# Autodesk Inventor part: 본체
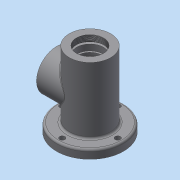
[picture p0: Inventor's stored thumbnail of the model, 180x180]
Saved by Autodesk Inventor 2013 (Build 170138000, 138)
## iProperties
Created: 2016-08
Part Number: 본체
Material: 일반
Document SubType Name: Modeling
Designer: dgall
Density: 1 g/cm^3
Author: dgall
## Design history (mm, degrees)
sketch "스케치1"
  geometry: C1 r 31 at (0, 0); 1 further point
  constraints: 1 centre point, 1 coincident
  dimensions: "d0" = 62 diameter of C1
extrude "돌출1" new body sketch "스케치1" distance "d2" = 115; taper "d3" = 0 deg
node "작업 평면1"
sketch "스케치2"
  geometry: C1 r 50 at (0, 0); 1 further point
  constraints: 1 centre point, 1 coincident
  dimensions: "d5" = 100 diameter of C1
extrude "돌출2" join sketch "스케치2" distance "d7" = 13; taper "d8" = 0 deg
node "작업 평면2"
sketch "스케치4" dims "d14" = 83
  geometry: L1 (0, 0)-(0, 41.5); C1 r 31 at (0, 0) reference; C2 r 4 at (0, 41.5)
  constraints: 2 coincident, 2 end point, 1 centre point, 1 vertical, 1 vertical alignment, 2 other
  dimensions: "d16" = 8 diameter of C2
extrude "돌출4" cut sketch "스케치4" stored distance "d17" = 13; taper "d18" = 0 deg
fillet "모깎기1" dims "d22" = 3
sketch "스케치5"
  geometry: C1 r 31 at (0, 0) reference
hole "구멍1" sketch "스케치5" at (0, 0) diameter "d23" = 40.376; stored, may be unused: countersink angle "d27" = 90 deg, drill point angle "d29" = 0 deg; dims "d24" = 6, "d25" = 4, "d26" = 2, "d28" = 9
sketch "스케치6"
  geometry: C1 r 20.188 at (0, 0) reference; C2 r 24 at (0, 0)
  constraints: 1 centre point, 1 coincident
  dimensions: "d30" = 48 diameter of C2
extrude "돌출5" cut sketch "스케치6" distance "d32" = 3; taper "d33" = 0 deg
sketch "스케치7"
  geometry: C1 r 24 at (0, 0) reference; C2 r 20 at (0, 0)
  constraints: 1 centre point, 1 coincident
  dimensions: "d34" = 40 diameter of C2
extrude "돌출6" cut sketch "스케치7" distance "d36" = 9; taper "d37" = 0 deg
fillet "모깎기2" dims "d50" = 3
sketch "스케치9"
  geometry: C1 r 20 at (0, 0) reference; C2 r 17.5 at (0, 0)
  constraints: 1 centre point, 1 coincident
  dimensions: "d52" = 35 diameter of C2
extrude "돌출7" cut sketch "스케치9" distance "d54" = 3.75; taper "d55" = 0 deg
sketch "스케치10"
  geometry: C1 r 17.5 at (0, 0) reference; C2 r 18.5 at (0, 0)
  constraints: 1 centre point, 1 coincident
  dimensions: "d56" = 37 diameter of C2
extrude "돌출8" cut sketch "스케치10" distance "d58" = 1.75; taper "d59" = 0 deg
sketch "스케치11"
  geometry: C1 r 18.5 at (0, 0) reference; C2 r 17.5 at (0, 0)
  constraints: 1 centre point, 1 coincident
  dimensions: "d60" = 35 diameter of C2
extrude "돌출9" cut sketch "스케치11" distance "d62" = 11; taper "d63" = 0 deg
chamfer "모따기1" distance "d64" = 1; stored, may be unused: second distance "d65" = 2, angle "d66" = 45 deg
sketch "스케치12"
  geometry: C1 r 16.5 at (0, 0) reference; C2 r 26 at (0, 0)
  constraints: 1 centre point, 1 coincident
  dimensions: "d67" = 52 diameter of C2
extrude "돌출10" cut sketch "스케치12" distance "d69" = 38; taper "d70" = 0 deg
sketch "스케치13"
  geometry: C1 r 26 at (0, 0) reference; C2 r 17.5 at (0, 0)
  constraints: 1 centre point, 1 coincident
  dimensions: "d71" = 35 diameter of C2
extrude "돌출11" cut sketch "스케치13" distance "d73" = 11; taper "d74" = 0 deg
chamfer "모따기2" distance "d75" = 1; stored, may be unused: second distance "d76" = 2, angle "d77" = 45 deg
sketch "스케치14"
  geometry: C1 r 17.5 at (0, 0) reference; C2 r 16.5 at (0, 0)
  constraints: 1 centre point, 1 coincident
  dimensions: "d78" = 33 diameter of C2
extrude "돌출12" cut sketch "스케치14" distance "d80" = 5; taper "d81" = 0 deg
fillet "모깎기4" dims "d82" = 3
sketch "스케치15"
  geometry: C1 r 13.5 at (0, 0) reference; C2 r 10 at (0, 0)
  constraints: 1 centre point, 1 coincident
  dimensions: "d83" = 20 diameter of C2
sketch "스케치18"
  geometry: L1 (0, 0)-(0, 37.8); L2 (21, 0)-(16, 14); L3 (16, 14)-(0, 14); L4 (-31, 0)-(31, 0) reference; L5 (21, 0)-(0, 0)
  constraints: 8 end point, 1 perpendicular, 1 point on line, 1 vertical
  dimensions: "d101" = 42 diameter of L2.start L1; "d103" = 32 diameter of L2.end L1; "d104" = 14 vertical distance of L2.start L2.end; "d105" = 0 distance from line of L4 L2.start
revolve "회전1" sketch "스케치18" stored, may be unused: angle "d106" = 90 deg
fillet "모깎기5" dims "d107" = 3
extrude "돌출16" cut sketch "스케치15" distance "d108" = 2.7; taper "d109" = 0 deg
sketch "스케치19"
  geometry: C1 r 10 at (0, 0) reference; C2 r 12.5 at (0, 0)
  constraints: 1 centre point, 1 coincident
  dimensions: "d110" = 25 diameter of C2
extrude "돌출17" cut sketch "스케치19" stored distance "d112" = 2.7; taper "d113" = 0 deg
chamfer "모따기5" distance "d114" = 0.7; stored, may be unused: second distance "d115" = 2, angle "d116" = 30 deg
node "작업 평면3"
node "작업 평면4"
node "작업 평면5"
node "작업 평면6"
sketch "스케치23"
  geometry: L1 (31, 115)-(-31, 115) reference; L2 (0, 115)-(0, 59); C1 r 30 at (0, 59); 1 further point
  constraints: 2 end point, 1 centre point, 1 coincident, 1 midpoint, 1 perpendicular
  dimensions: "d123" = 56 distance of L2.start L2.end; "d125" = 60 diameter of C1
extrude "돌출18" join sketch "스케치23" stored distance "d126" = 2.7; taper "d127" = 0 deg
sketch "스케치24"
  geometry: C1 r 30 at (0, 0) reference; C2 r 19 at (0, 0); 1 further point
  constraints: 1 centre point, 1 coincident
  dimensions: "d128" = 38 diameter of C2
extrude "돌출19" cut sketch "스케치24" stored distance "d130" = 2.7; taper "d131" = 0 deg
sketch "스케치25" dims "d132" = 48
  geometry: L1 (0, 0)-(0, 24); C1 r 30 at (0, 0) reference; 1 further point
  constraints: 2 end point, 1 coincident, 1 vertical, 1 vertical alignment, 2 other
hole "구멍3" sketch "스케치25" at (0, 24) diameter "d134" = 3.242; stored, may be unused: countersink angle "d138" = 90 deg, drill point angle "d140" = 118 deg; dims "d135" = 8, "d136" = 4, "d137" = 2, "d139" = 10
chamfer "모따기6" distance "d144" = 1; stored, may be unused: second distance "d145" = 2, angle "d146" = 30 deg
node "작업 평면7"
sketch "스케치26"
  geometry: L1 (43.002, 79.739)-(43.002, 38.261); L2 (43.002, 38.261)-(36.998, 38.261); L3 (36.998, 38.261)-(36.998, 79.739); L4 (36.998, 79.739)-(43.002, 79.739); L5 (40, 79.739)-(40, 38.261); L6 (43.002, 59)-(36.998, 59); L7 (31, 115)-(-31, 115) reference; L8 (50, 89)-(50, 29) reference; 1 further point
  constraints: 4 end point, 4 midpoint, 2 other
  dimensions: "d148" = 56 distance from line of L6.start L7; "d149" = 10 distance from line of L5.end L8
feature "엠보싱2" sketch "스케치26" dims "d150" = 0.5, "d151" = 0
fillet "모깎기6" dims "d152" = 3
node "솔리드1"
pattern_circular "원형 패턴1" dims angle "d20" = 360 deg
pattern_circular "원형 패턴3" dims angle "d142" = 360 deg
other parameters: "d4" = 3, "d117" = 44.75, "d147" = 37
